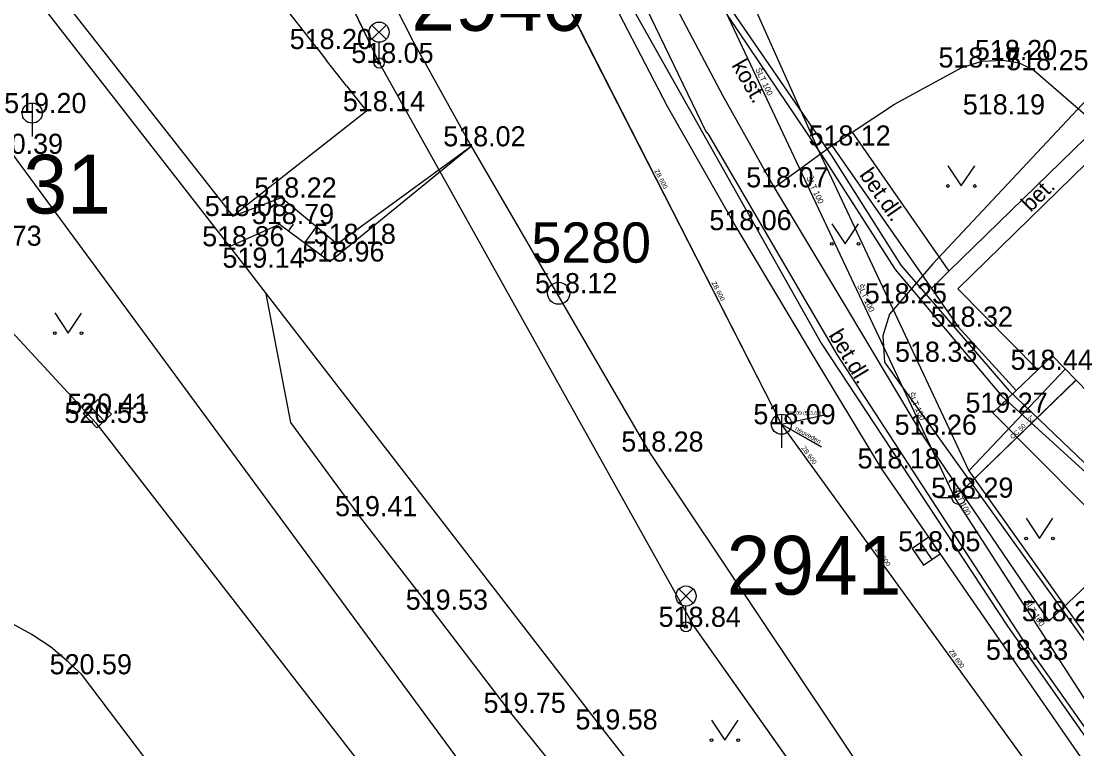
# Model space of a CAD drawing. Extents: x -668867 to -667827, y -1131943 to -1131019.
# Drawn here: x -668559.51 to -668520.13, y -1131166.04 to -1131138.89 of the extents above; entities that cross this region are included whole.
import ezdxf

# ---------------------------------------------------------------- set-up
doc = ezdxf.new("R2010")
doc.units = 0
for name, color, linetype in [('G_Bod_tecka', 7, 'Continuous'), ('G_Bod_vyska', 7, 'Continuous'), ('G_Bodove_pole', 7, 'Continuous'), ('G_Breh_Teren', 7, 'Continuous'), ('G_Budovy_Objekty', 7, 'Continuous'), ('G_Budovy_vstupy', 7, 'Continuous'), ('G_Cesty_Schody', 7, 'Continuous'), ('G_Objekty_technicke', 7, 'Continuous'), ('G_Plochy_zpevnene', 7, 'Continuous'), ('G_Ploty', 7, 'Continuous'), ('G_Ploty_vstupy', 7, 'Continuous'), ('G_Popisy_povrchu', 7, 'Continuous'), ('G_Site-kanalizace', 7, 'Continuous'), ('G_Site-vodovod', 7, 'Continuous'), ('G_Vyskove_srafy', 7, 'Continuous'), ('G_Z_ELsilove_podz_kotovane', 7, 'Continuous'), ('G_Z_KANAL_podz_kotovane', 7, 'Continuous'), ('G_Z_PLYNY_podz_geodeticky', 7, 'Continuous'), ('G_Z_PLYNY_podz_priblizne', 7, 'Continuous'), ('G_Z_SPOJE_podz_geodeticky', 7, 'Continuous'), ('G_Z_SPOJE_podz_kotovane', 7, 'Continuous'), ('G_Z_SPOJE_podz_priblizne', 7, 'Continuous'), ('G_Z_VODA_podz_kotovane', 7, 'Continuous'), ('G_Zelen-Znacky', 7, 'Continuous'), ('Vrstva 1', 7, 'Continuous'), ('Vrstva 10', 7, 'Continuous'), ('Vrstva 13', 7, 'Continuous'), ('Vrstva 17', 7, 'Continuous'), ('Vrstva 2', 7, 'Continuous'), ('Vrstva 25', 7, 'Continuous'), ('Vrstva 27', 7, 'Continuous'), ('Vrstva 3', 7, 'Continuous'), ('Vrstva 4', 7, 'Continuous'), ('Vrstva 6', 7, 'Continuous'), ('Vrstva 8', 7, 'Continuous')]:
    doc.layers.add(name, color=color, linetype=linetype)

msp = doc.modelspace()

# ---------------------------------------------------------------- linework, layer by layer
at = {"layer": 'G_Bod_tecka'}
for p, q in [((-668548.45, -1131139.93), (-668548.45, -1131139.93)), ((-668546.16, -1131140.45), (-668546.16, -1131140.45)), ((-668522.89, -1131140.34), (-668522.89, -1131140.34)), ((-668524.42, -1131140.62), (-668524.42, -1131140.62)), ((-668521.74, -1131140.72), (-668521.74, -1131140.72)), ((-668559.1, -1131142.32), (-668559.1, -1131142.32)), ((-668546.63, -1131142.25), (-668546.63, -1131142.25)), ((-668523.5, -1131142.37), (-668523.5, -1131142.37)), ((-668542.72, -1131143.56), (-668542.72, -1131143.56)), ((-668529.27, -1131143.53), (-668529.27, -1131143.53)), ((-668531.42, -1131145.09), (-668531.42, -1131145.09)), ((-668549.8, -1131145.47), (-668549.8, -1131145.47)), ((-668551.62, -1131146.16), (-668551.62, -1131146.16)), ((-668549.88, -1131146.46), (-668549.88, -1131146.46)), ((-668532.78, -1131146.69), (-668532.78, -1131146.69)), ((-668547.72, -1131147.2), (-668547.72, -1131147.2)), ((-668551.72, -1131147.29), (-668551.72, -1131147.29)), ((-668548, -1131147.86), (-668548, -1131147.86)), ((-668551.12, -1131148.09), (-668551.12, -1131148.09)), ((-668539.46, -1131149.04), (-668539.46, -1131149.04)), ((-668527.02, -1131149.42), (-668527.02, -1131149.42)), ((-668524.56, -1131150.29), (-668524.56, -1131150.29)), ((-668525.89, -1131151.6), (-668525.89, -1131151.6)), ((-668521.58, -1131151.9), (-668521.58, -1131151.9)), ((-668523.26, -1131153.5), (-668523.26, -1131153.5)), ((-668556.72, -1131153.88), (-668556.72, -1131153.88)), ((-668556.67, -1131153.54), (-668556.67, -1131153.54)), ((-668531.15, -1131153.93), (-668531.15, -1131153.93)), ((-668525.9, -1131154.32), (-668525.9, -1131154.32)), ((-668536.1, -1131154.95), (-668536.1, -1131154.95)), ((-668527.43, -1131155.58), (-668527.43, -1131155.58)), ((-668524.54, -1131156.67), (-668524.54, -1131156.67)), ((-668546.84, -1131157.36), (-668546.84, -1131157.36)), ((-668525.75, -1131158.67), (-668525.75, -1131158.67)), ((-668544.14, -1131160.85), (-668544.14, -1131160.85)), ((-668521.17, -1131161.28), (-668521.17, -1131161.28)), ((-668534.71, -1131161.49), (-668534.71, -1131161.49)), ((-668522.51, -1131162.72), (-668522.51, -1131162.72)), ((-668557.26, -1131163.26), (-668557.26, -1131163.26)), ((-668541.25, -1131164.7), (-668541.25, -1131164.7)), ((-668537.81, -1131165.32), (-668537.81, -1131165.32))]:
    msp.add_line(p, q, dxfattribs=at)
at = {"layer": 'G_Bodove_pole'}
for radius in [0.412, 0.05]:
    msp.add_circle((-668539.46, -1131149.04), radius, dxfattribs=at)
at = {"layer": 'G_Breh_Teren'}
for points in [[(-668548, -1131147.86), (-668542.72, -1131143.56)], [(-668547.72, -1131147.2), (-668542.72, -1131143.56)], [(-668541.84, -1131168.29), (-668559.84, -1131143.84)], [(-668551.62, -1131146.16), (-668549.8, -1131145.47)], [(-668549.8, -1131145.47), (-668547.72, -1131147.2)], [(-668551.74, -1131147.3), (-668549.88, -1131146.46)], [(-668549.88, -1131146.46), (-668548, -1131147.86)], [(-668549.45, -1131153.86), (-668550.37, -1131149.07)], [(-668546.84, -1131157.42), (-668549.45, -1131153.86)], [(-668544.14, -1131160.9), (-668546.84, -1131157.42)], [(-668541.25, -1131164.7), (-668544.14, -1131160.9)], [(-668538.58, -1131168.01), (-668541.25, -1131164.7)]]:
    msp.add_lwpolyline(points, dxfattribs=at)
at = {"layer": 'G_Budovy_Objekty'}
for p, q in [((-668569.03, -1131123.97), (-668551.62, -1131146.16)), ((-668548.45, -1131139.93), (-668548.12, -1131140.36)), ((-668547.37, -1131141.3), (-668546.63, -1131142.25)), ((-668546.63, -1131142.25), (-668551.62, -1131146.16)), ((-668524.57, -1131148.88), (-668518.81, -1131143.25)), ((-668524.57, -1131148.88), (-668521.58, -1131151.9)), ((-668521.05, -1131151.37), (-668521.58, -1131151.9)), ((-668516.95, -1131155.58), (-668521.05, -1131151.37))]:
    msp.add_line(p, q, dxfattribs=at)
at = {"layer": 'G_Budovy_vstupy'}
for p, q in [((-668548.45, -1131139.93), (-668549.92, -1131138.03)), ((-668547.37, -1131141.3), (-668548.12, -1131140.36))]:
    msp.add_line(p, q, dxfattribs=at)
at = {"layer": 'G_Cesty_Schody'}
for points in [[(-668535.17, -1131138.22), (-668533.33, -1131141.68), (-668531.42, -1131145.09)], [(-668525.55, -1131148.86), (-668524.9, -1131148.22)], [(-668522.39, -1131152.67), (-668521.58, -1131151.9)]]:
    msp.add_lwpolyline(points, dxfattribs=at)
at = {"layer": 'G_Objekty_technicke'}
for p, q in [((-668546.425, -1131139.035), (-668545.895, -1131139.565)), ((-668546.425, -1131139.565), (-668545.895, -1131139.035)), ((-668546.16, -1131140.45), (-668546.16, -1131139.675)), ((-668534.975, -1131160.075), (-668534.445, -1131160.605)), ((-668534.975, -1131160.605), (-668534.445, -1131160.075)), ((-668534.71, -1131161.49), (-668534.71, -1131160.715))]:
    msp.add_line(p, q, dxfattribs=at)
for centre, radius in [((-668546.16, -1131139.3), 0.375), ((-668546.16, -1131140.45), 0.19), ((-668546.16, -1131140.45), 0.05), ((-668534.71, -1131160.34), 0.375), ((-668534.71, -1131161.49), 0.19), ((-668534.71, -1131161.49), 0.05)]:
    msp.add_circle(centre, radius, dxfattribs=at)
at = {"layer": 'G_Plochy_zpevnene'}
msp.add_line((-668548.18, -1131175.22), (-668557.26, -1131163.26), dxfattribs=at)
for points in [[(-668556.86, -1131114.73), (-668556.45, -1131115.66), (-668553.7, -1131121.6), (-668550.85, -1131127.49), (-668546.94, -1131135.61), (-668544.9, -1131139.62), (-668542.72, -1131143.56), (-668539.41, -1131149.26), (-668536.1, -1131154.95)], [(-668538.73, -1131115.7), (-668540.16, -1131117.07), (-668541.11, -1131118.23), (-668542.29, -1131120.12), (-668543.13, -1131122.14), (-668543.38, -1131123.52), (-668543.37, -1131124.6), (-668543.06, -1131126.22), (-668542.49, -1131127.74), (-668537.86, -1131137.34), (-668535.41, -1131142.06), (-668532.78, -1131146.69), (-668530.11, -1131151.14), (-668527.43, -1131155.58)], [(-668528.51, -1131143.03), (-668526.93, -1131141.99), (-668524.42, -1131140.62), (-668523.66, -1131140.38), (-668522.89, -1131140.34), (-668522.28, -1131140.44), (-668521.74, -1131140.72), (-668520.54, -1131141.75), (-668519.34, -1131142.79)], [(-668524.9, -1131148.22), (-668519.34, -1131142.79)], [(-668531.42, -1131145.09), (-668530.34, -1131144.31), (-668529.27, -1131143.53), (-668528.51, -1131143.03)], [(-668528.51, -1131143.03), (-668524.9, -1131148.22)], [(-668529.27, -1131143.53), (-668525.55, -1131148.86)], [(-668531.42, -1131145.09), (-668528.66, -1131149.7), (-668525.9, -1131154.32)], [(-668563.01, -1131147.08), (-668556.72, -1131153.88)], [(-668525.55, -1131148.86), (-668524.56, -1131150.29)], [(-668524.56, -1131150.29), (-668522.39, -1131152.67)], [(-668523.26, -1131153.5), (-668522.39, -1131152.67)], [(-668518.28, -1131158.53), (-668523.26, -1131153.5)], [(-668556.72, -1131153.88), (-668544.1, -1131170.16)], [(-668525.9, -1131154.32), (-668521.17, -1131161.28)], [(-668536.1, -1131154.95), (-668530.57, -1131163.21), (-668525.05, -1131171.47), (-668520.52, -1131178.02), (-668515.88, -1131184.51), (-668510.45, -1131192.02), (-668504.86, -1131199.41), (-668501.67, -1131203.45), (-668498.48, -1131207.48)], [(-668527.43, -1131155.58), (-668524.97, -1131159.15), (-668522.51, -1131162.72), (-668519.01, -1131167.77), (-668515.51, -1131172.82), (-668510.81, -1131179.58), (-668506.02, -1131186.29), (-668503.7, -1131189.39), (-668501.33, -1131192.45), (-668495.43, -1131200.02), (-668489.54, -1131207.58)], [(-668521.17, -1131161.28), (-668518.28, -1131158.53)], [(-668557.26, -1131163.26), (-668557.51, -1131163.03), (-668557.76, -1131162.79), (-668558.42, -1131162.24), (-668559.14, -1131161.76), (-668560.34, -1131161.1), (-668561.59, -1131160.55), (-668563.22, -1131159.96), (-668564.9, -1131159.54), (-668566.69, -1131159.31), (-668568.48, -1131159.26), (-668569.65, -1131159.3), (-668570.81, -1131159.43), (-668572.12, -1131159.64), (-668573.43, -1131159.86)]]:
    msp.add_lwpolyline(points, dxfattribs=at)
at = {"layer": 'G_Ploty'}
for p, q in [((-668566.6, -1131128.2), (-668551.74, -1131147.3)), ((-668551.74, -1131147.3), (-668551.12, -1131148.09)), ((-668550.37, -1131149.07), (-668537.81, -1131165.32)), ((-668537.81, -1131165.32), (-668528.63, -1131176.99))]:
    msp.add_line(p, q, dxfattribs=at)
at = {"layer": 'G_Ploty_vstupy'}
msp.add_line((-668551.12, -1131148.09), (-668550.37, -1131149.07), dxfattribs=at)
at = {"layer": 'G_Site-kanalizace'}
for p, q in [((-668559.1, -1131141.945), (-668559.1, -1131143.194)), ((-668556.927, -1131153.267), (-668556.413, -1131153.813)), ((-668531.15, -1131153.555), (-668531.15, -1131154.805)), ((-668525.962, -1131158.361), (-668525.538, -1131158.979))]:
    msp.add_line(p, q, dxfattribs=at)
for points in [[(-668557.199, -1131153.524), (-668556.685, -1131154.069), (-668556.139, -1131153.555), (-668556.654, -1131153.009)], [(-668526.271, -1131158.572), (-668525.846, -1131159.191), (-668525.228, -1131158.767), (-668525.652, -1131158.148)]]:
    msp.add_lwpolyline(points, close=True, dxfattribs=at)
for centre in [(-668559.1, -1131142.32), (-668531.15, -1131153.93)]:
    msp.add_circle(centre, 0.375, dxfattribs=at)
at = {"layer": 'G_Site-vodovod'}
for p, q in [((-668524.79, -1131156.67), (-668525.29, -1131156.67)), ((-668524.29, -1131156.67), (-668523.79, -1131156.67))]:
    msp.add_line(p, q, dxfattribs=at)
msp.add_circle((-668524.54, -1131156.67), 0.25, dxfattribs=at)
at = {"layer": 'G_Vyskove_srafy'}
for points in [[(-668549.54, -1131146.72), (-668549.35, -1131146.46)], [(-668548.93, -1131147.16), (-668548.49, -1131146.56)], [(-668548.33, -1131147.61), (-668548.16, -1131147.38)]]:
    msp.add_lwpolyline(points, dxfattribs=at)
at = {"layer": 'G_Z_ELsilove_podz_kotovane'}
for points in [[(-668555.398, -1131094.402), (-668552.424, -1131100.994), (-668549.819, -1131105.896), (-668549.036, -1131109.044), (-668543.513, -1131123.011), (-668538.77, -1131133.046), (-668533.966, -1131143.005), (-668533.886, -1131143.112), (-668529.079, -1131151.328), (-668522.184, -1131161.928), (-668516.261, -1131170.305), (-668508.028, -1131181.583), (-668500.536, -1131191.955), (-668492.492, -1131202.47), (-668484.337, -1131212.694), (-668478.332, -1131220.418)], [(-668557.051, -1131095.523), (-668556.743, -1131096.102), (-668553.492, -1131102.946), (-668550.913, -1131106.998), (-668549.012, -1131109.978), (-668547.955, -1131112.287), (-668546.633, -1131115.322), (-668544.714, -1131119.434), (-668543.785, -1131121.123), (-668541.478, -1131124.83), (-668538.089, -1131130.556), (-668535.412, -1131135.334), (-668534.618, -1131136.572), (-668534.429, -1131136.881), (-668533.477, -1131138.214), (-668529.506, -1131144.107), (-668526.905, -1131148.152), (-668522.931, -1131152.878), (-668519.382, -1131156.103)], [(-668561.16, -1131106.51), (-668559.79, -1131110.01), (-668559.58, -1131111.71), (-668559.44, -1131112.79), (-668559.17, -1131113.36), (-668546.16, -1131140.45), (-668534.4, -1131161.49), (-668517.32, -1131185.65), (-668499.12, -1131209.6), (-668480.38, -1131233.31), (-668462.37, -1131256.28), (-668449.58, -1131276.8), (-668449.84, -1131279.37), (-668430.91, -1131303.38), (-668427.62, -1131304.54), (-668413.74, -1131320.95)], [(-668533.267, -1131138.122), (-668529.27, -1131143.924), (-668526.701, -1131147.993), (-668522.663, -1131152.674), (-668519.274, -1131155.919)]]:
    msp.add_lwpolyline(points, dxfattribs=at)
at = {"layer": 'G_Z_KANAL_podz_kotovane'}
for p, q in [((-668531.15, -1131153.93), (-668549.94, -1131117.09)), ((-668531.15, -1131153.93), (-668529.53, -1131153.58)), ((-668502.59, -1131193.3), (-668531.15, -1131153.93)), ((-668531.15, -1131153.93), (-668529.67, -1131154.77))]:
    msp.add_line(p, q, dxfattribs=at)
at = {"layer": 'G_Z_PLYNY_podz_geodeticky'}
for points in [[(-668529.76, -1131143.74), (-668524.16, -1131155.67), (-668491.6, -1131201.52), (-668457.62, -1131243.27), (-668455.9, -1131245.37), (-668427.25, -1131279.92), (-668424.99, -1131282.65)], [(-668524.16, -1131155.67), (-668520.56, -1131151.87)]]:
    msp.add_lwpolyline(points, dxfattribs=at)
at = {"layer": 'G_Z_PLYNY_podz_priblizne'}
msp.add_lwpolyline([(-668546.79, -1131105.63), (-668529.76, -1131143.74)], dxfattribs=at)
at = {"layer": 'G_Z_SPOJE_podz_geodeticky'}
msp.add_lwpolyline([(-668512.75, -1131134.42), (-668513.64, -1131135.27), (-668525.5, -1131147.94), (-668527.12, -1131149.82), (-668527.37, -1131150.63), (-668527.3, -1131151.61), (-668517.96, -1131164.64)], dxfattribs=at)
at = {"layer": 'G_Z_SPOJE_podz_kotovane'}
for points in [[(-668538.05, -1131107.48), (-668541.02, -1131108.79), (-668541.35, -1131109.82), (-668535.86, -1131115.82), (-668534.58, -1131115.3), (-668531.82, -1131117.98), (-668536.77, -1131123.07), (-668537.78, -1131123.05), (-668538.54, -1131123.66), (-668538.88, -1131123.92), (-668539.22, -1131123.89), (-668541.22, -1131123.43), (-668541.47, -1131123.37), (-668542.59, -1131124.18), (-668542.56, -1131126.14), (-668537.42, -1131137.13), (-668529.67, -1131150.9), (-668522.72, -1131161.47), (-668503.3, -1131189.1), (-668501.247, -1131191.625)], [(-668512.75, -1131134.42), (-668513.64, -1131135.27), (-668525.5, -1131147.94), (-668527.12, -1131149.82), (-668527.37, -1131150.63), (-668527.3, -1131151.61), (-668517.96, -1131164.64)]]:
    msp.add_lwpolyline(points, dxfattribs=at)
at = {"layer": 'G_Z_SPOJE_podz_priblizne'}
msp.add_lwpolyline([(-668512.75, -1131134.42), (-668513.64, -1131135.27), (-668525.5, -1131147.94), (-668527.12, -1131149.82), (-668527.37, -1131150.63), (-668527.3, -1131151.61), (-668517.96, -1131164.64)], dxfattribs=at)
at = {"layer": 'G_Z_VODA_podz_kotovane'}
for points in [[(-668554.356, -1131093.695), (-668553.39, -1131095.66), (-668547.53, -1131106.87), (-668547.37, -1131107.14), (-668535.16, -1131134.42), (-668524.68, -1131156.69), (-668524.68, -1131156.69), (-668514.04, -1131173.18), (-668502.91, -1131189.19), (-668501.17, -1131191.76), (-668498.15, -1131195.68), (-668493.12, -1131202.03), (-668493.02, -1131202.16), (-668492.31, -1131203.14)], [(-668524.68, -1131156.69), (-668524.52, -1131156.52), (-668520.15, -1131152.27)]]:
    msp.add_lwpolyline(points, dxfattribs=at)
at = {"layer": 'G_Zelen-Znacky'}
for p, q in [((-668524.94, -1131144.29), (-668524.44, -1131145.04)), ((-668524.44, -1131145.04), (-668523.94, -1131144.29)), ((-668529.27, -1131146.45), (-668528.77, -1131147.2)), ((-668528.77, -1131147.2), (-668528.27, -1131146.45)), ((-668558.26, -1131149.779), (-668557.76, -1131150.53)), ((-668557.76, -1131150.53), (-668557.26, -1131149.78)), ((-668522.02, -1131157.44), (-668521.52, -1131158.19)), ((-668521.52, -1131158.19), (-668521.02, -1131157.44)), ((-668533.76, -1131164.97), (-668533.26, -1131165.72)), ((-668533.26, -1131165.72), (-668532.76, -1131164.97))]:
    msp.add_line(p, q, dxfattribs=at)
for centre in [(-668524.94, -1131145.04), (-668523.94, -1131145.04), (-668529.27, -1131147.2), (-668528.27, -1131147.2), (-668558.26, -1131150.531), (-668557.26, -1131150.531), (-668522.02, -1131158.19), (-668521.02, -1131158.19), (-668533.76, -1131165.72), (-668532.76, -1131165.72)]:
    msp.add_circle(centre, 0.05, dxfattribs=at)
at = {"layer": 'Vrstva 1'}
for p, q in [((-668546.16, -1131140.45), (-668546.16, -1131140.45)), ((-668534.4, -1131161.49), (-668534.4, -1131161.49))]:
    msp.add_line(p, q, dxfattribs=at)
at = {"layer": 'Vrstva 10'}
for p, q in [((-668531.151, -1131153.926), (-668549.938, -1131117.085)), ((-668502.587, -1131193.304), (-668531.151, -1131153.926))]:
    msp.add_line(p, q, dxfattribs=at)
at = {"layer": 'Vrstva 13'}
for q in [(-668529.526, -1131153.578), (-668529.672, -1131154.766)]:
    msp.add_line((-668531.151, -1131153.926), q, dxfattribs=at)
at = {"layer": 'Vrstva 17'}
for p, q in [((-668559.17, -1131113.36), (-668546.16, -1131140.45)), ((-668546.16, -1131140.45), (-668534.4, -1131161.49)), ((-668534.4, -1131161.49), (-668517.32, -1131185.65))]:
    msp.add_line(p, q, dxfattribs=at)
at = {"layer": 'Vrstva 25'}
msp.add_lwpolyline([(-668524.679, -1131156.689), (-668524.524, -1131156.52), (-668520.146, -1131152.272)], dxfattribs=at)
at = {"layer": 'Vrstva 27'}
msp.add_lwpolyline([(-668554.359, -1131093.697), (-668553.394, -1131095.659), (-668547.53, -1131106.872), (-668547.372, -1131107.14), (-668535.158, -1131134.419), (-668524.68, -1131156.688), (-668524.679, -1131156.689), (-668514.04, -1131173.182), (-668502.909, -1131189.194), (-668501.166, -1131191.758), (-668498.148, -1131195.679), (-668493.124, -1131202.026), (-668493.025, -1131202.162), (-668492.315, -1131203.139)], dxfattribs=at)
at = {"layer": 'Vrstva 6'}
msp.add_line((-668524.524, -1131156.52), (-668524.524, -1131156.52), dxfattribs=at)
at = {"layer": 'Vrstva 8'}
msp.add_line((-668531.151, -1131153.926), (-668531.151, -1131153.926), dxfattribs=at)

# ---------------------------------------------------------------- texts
at = {"layer": 'G_Bod_vyska'}
for s, p in [('518.20', (-668549.494, -1131139.93)), ('518.05', (-668547.194, -1131140.45)), ('518.20', (-668523.934, -1131140.34)), ('518.17', (-668525.291, -1131140.62)), ('518.25', (-668522.762, -1131140.72)), ('519.20', (-668560.146, -1131142.32)), ('518.14', (-668547.511, -1131142.25)), ('518.19', (-668524.383, -1131142.37)), ('518.02', (-668543.764, -1131143.56)), ('518.12', (-668530.141, -1131143.53)), ('520.39', (-668561.018, -1131143.84)), ('518.07', (-668532.464, -1131145.09)), ('518.22', (-668550.812, -1131145.47)), ('518.08', (-668552.664, -1131146.16)), ('518.79', (-668550.904, -1131146.46)), ('518.06', (-668533.838, -1131146.69)), ('518.18', (-668548.601, -1131147.2)), ('520.73', (-668561.816, -1131147.27)), ('518.86', (-668552.756, -1131147.29)), ('518.96', (-668549.028, -1131147.86)), ('519.14', (-668552.003, -1131148.09)), ('518.12', (-668540.341, -1131149.04)), ('518.25', (-668528.042, -1131149.42)), ('518.32', (-668525.582, -1131150.29)), ('518.33', (-668526.912, -1131151.6)), ('518.44', (-668522.602, -1131151.9)), ('519.27', (-668524.284, -1131153.5)), ('520.53', (-668557.896, -1131153.88)), ('520.41', (-668557.794, -1131153.54)), ('518.09', (-668532.196, -1131153.93)), ('518.26', (-668526.926, -1131154.32)), ('518.28', (-668537.122, -1131154.95)), ('518.18', (-668528.311, -1131155.58)), ('518.29', (-668525.564, -1131156.67)), ('519.41', (-668547.803, -1131157.36)), ('518.05', (-668526.794, -1131158.67)), ('519.53', (-668545.164, -1131160.85)), ('518.29', (-668522.184, -1131161.28)), ('518.84', (-668535.732, -1131161.49)), ('518.33', (-668523.522, -1131162.72)), ('520.59', (-668558.448, -1131163.26)), ('519.75', (-668542.264, -1131164.7)), ('519.58', (-668538.834, -1131165.32))]:
    msp.add_text(s, height=0.75, dxfattribs=at).set_placement(p)
at = {"layer": 'G_Bodove_pole'}
msp.add_text('5280', height=1.5, dxfattribs=at).set_placement((-668540.478, -1131147.9))
at = {"layer": 'G_Popisy_povrchu'}
for s, rotation, p in [('kost.', 299.9396, (-668533.025, -1131140.536)), ('bet.dl.', 304.8345, (-668528.265, -1131144.625)), ('bet.', 44.3332, (-668521.853, -1131146.036)), ('bet.dl.', 300.9997, (-668529.41, -1131150.606))]:
    msp.add_text(s, height=0.6, rotation=rotation, dxfattribs=at).set_placement(p)
at = {"layer": 'Vrstva 2'}
msp.add_text('518.09 (513.66)', height=0.13163, dxfattribs=at).set_placement((-668530.945, -1131153.573))
at = {"layer": 'Vrstva 3'}
for s, rotation, p in [('ZB 600', 297.0637, (-668535.893, -1131144.473)), ('ZB 600', 297.0006, (-668533.761, -1131148.651)), ('neuveden', 330.395, (-668530.658, -1131154.145)), ('ZB 600', 305.908, (-668530.418, -1131154.816)), ('ZB 600', 305.9737, (-668527.664, -1131158.614)), ('ZB 600', 305.908, (-668524.909, -1131162.41))]:
    msp.add_text(s, height=0.1755, rotation=rotation, dxfattribs=at).set_placement(p)
at = {"layer": 'Vrstva 4'}
for s, p in [('2940', (-668544.957, -1131139.249)), ('31', (-668559.427, -1131146.068)), ('2941', (-668533.197, -1131160.289))]:
    msp.add_text(s, height=2.1939, dxfattribs=at).set_placement(p)
for s, height, rotation, p in [('ŠLT 100', 0.2194, 295.1981, (-668532.13, -1131140.689)), ('ŠLT 100', 0.2194, 295.1981, (-668530.23, -1131144.725)), ('ŠLT 100', 0.2194, 295.192, (-668528.332, -1131148.762)), ('ŠLT 100', 0.2194, 295.166, (-668526.432, -1131152.798)), ('OC 50 - 2"', 0.1755, 44.2244, (-668522.519, -1131154.498)), ('ŠLT 100', 0.2194, 296.2014, (-668524.758, -1131156.359)), ('ŠLT 100', 0.2194, 302.8386, (-668522.097, -1131160.562))]:
    msp.add_text(s, height=height, rotation=rotation, dxfattribs=at).set_placement(p)

doc.saveas('drawing.dxf')
